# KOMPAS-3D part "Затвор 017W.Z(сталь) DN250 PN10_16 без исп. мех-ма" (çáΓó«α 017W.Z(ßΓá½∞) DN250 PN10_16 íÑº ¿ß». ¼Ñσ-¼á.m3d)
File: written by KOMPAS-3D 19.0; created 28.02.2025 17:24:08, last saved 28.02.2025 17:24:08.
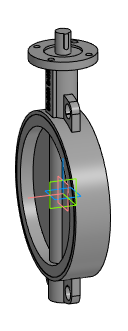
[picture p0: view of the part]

Document properties: Автор: Евгений; Полное имя файла: E:\Dendor Работа Сачек\3D для проекитирвщиков\1.5 Тип 017W.Z Сталь Затвор дисковый поворотный Межфланцевый\stp_Тип 017W.Z(сталь). Затвор без исполн. механизма\Затвор 017W.Z(сталь) DN250 PN10_16 без исп. мех-ма.m3d

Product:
- Part/product: Затвор 017W.Z(сталь) DN250 PN10_16 без исп. мех-ма

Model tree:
1. Операция без истории:1  (labels: Затвор 017W.Z(сталь) DN250 PN10_16 без исп. мех-ма)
